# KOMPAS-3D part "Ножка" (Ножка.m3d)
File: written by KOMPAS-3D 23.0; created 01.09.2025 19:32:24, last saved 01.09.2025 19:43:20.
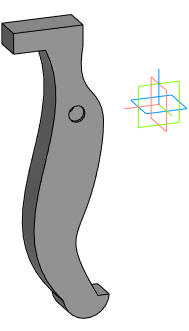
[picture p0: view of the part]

Document properties: Автор: Inspektor_Kot; Полное имя файла: I:\Autodesk Inventor Projects\ИМ-ИТ ЦД\Вариант 3\Ножка.m3d

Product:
- Part/product: Ножка
    Масса: 5.058903

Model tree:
1. Эскиз:1  (with: Элемент выдавливания:1, Элемент выдавливания:4)
2. Элемент выдавливания:2
     Расстояние 1 = 4
3. Эскиз:2  (with: Элемент выдавливания:2)
4. Элемент выдавливания:3
     Расстояние 1 = 30
5. Эскиз:3  (with: Элемент выдавливания:3, Элемент выдавливания:2)
6. Элемент выдавливания:4
     Расстояние 1 = 4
